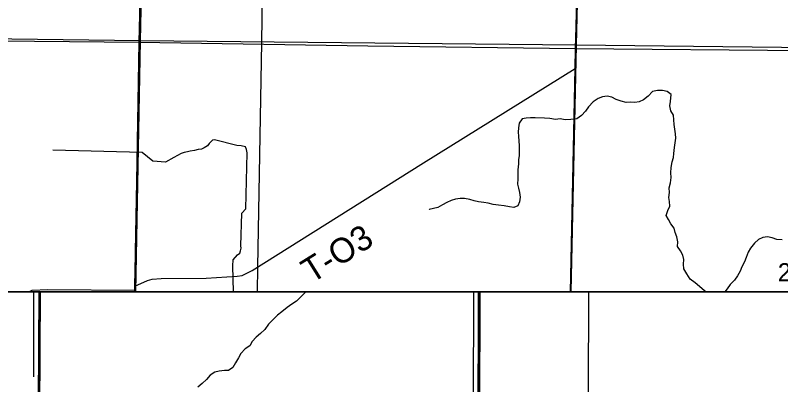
# Model space of a CAD drawing. Extents: x -6.2 to 37.4, y 0.2 to 22.2.
# Drawn here: x 5.676 to 6.554, y 17.601 to 18.025 of the extents above; entities that cross this region are included whole.
import ezdxf

# ---------------------------------------------------------------- set-up
doc = ezdxf.new("R2010")
doc.units = 0
for name, color, linetype in [('GM_X_County_Road', 7, 'Continuous'), ('GM_X_Minor_River', 7, 'Continuous'), ('GM_X_Rail_Line', 7, 'Continuous'), ('GM_X_Section', 7, 'Continuous'), ('GM_X_Section_Text', 7, 'Continuous'), ('GM_X_State_Route', 7, 'Continuous'), ('GM_X_Township_Road', 7, 'Continuous'), ('GM_X_Township_Road_Text', 7, 'Continuous'), ('GM_X_US_Shield', 7, 'Continuous'), ('SH_Border', 7, 'Continuous'), ('SH_Cut_Line', 7, 'Continuous')]:
    doc.layers.add(name, color=color, linetype=linetype)

msp = doc.modelspace()

# ---------------------------------------------------------------- linework, layer by layer
at = {"layer": 'GM_X_County_Road'}
msp.add_lwpolyline([(5.44297, 17.99748), (5.45798, 17.99734), (5.81851, 17.99391), (6.08058, 17.98981), (6.31898, 17.9868), (6.58277, 17.9842), (6.78688, 17.98297), (6.82357, 17.99459)], dxfattribs=at)
at = {"layer": 'GM_X_Minor_River'}
for p, q in [((5.69738, 17.70742), (5.69714, 17.61009)), ((6.20166, 17.70742), (6.20111, 17.43298))]:
    msp.add_line(p, q, dxfattribs=at)
for points in [[(6.46898, 17.70742), (6.46647, 17.70917), (6.45605, 17.71773), (6.45047, 17.7222), (6.44662, 17.72816), (6.44314, 17.73392), (6.44268, 17.73924), (6.44298, 17.74454), (6.44177, 17.74969), (6.43903, 17.75449), (6.43591, 17.75948), (6.43602, 17.76479), (6.43501, 17.7705), (6.43322, 17.77566), (6.432, 17.78043), (6.42794, 17.78544), (6.42539, 17.79043), (6.42284, 17.79522), (6.42485, 17.80068), (6.42704, 17.80595), (6.42677, 17.81107), (6.42592, 17.81583), (6.42661, 17.82132), (6.42634, 17.82683), (6.4276, 17.83268), (6.42867, 17.83854), (6.42822, 17.84405), (6.42835, 17.85031), (6.4298, 17.85654), (6.43104, 17.86145), (6.43171, 17.86637), (6.43242, 17.87318), (6.43291, 17.87829), (6.43397, 17.88377), (6.43351, 17.88891), (6.43267, 17.89423), (6.43202, 17.89937), (6.43157, 17.90488), (6.43112, 17.9102), (6.428, 17.91519), (6.42698, 17.92072), (6.42785, 17.92582), (6.42858, 17.93377), (6.42373, 17.93728), (6.41846, 17.93853), (6.41278, 17.93845), (6.40708, 17.93724), (6.40204, 17.93184), (6.39685, 17.92777), (6.39169, 17.9256), (6.38694, 17.92474), (6.38184, 17.92504), (6.37691, 17.92475), (6.37126, 17.9262), (6.36525, 17.92821), (6.36039, 17.93097), (6.35511, 17.93202), (6.3496, 17.93118), (6.34483, 17.92938), (6.33907, 17.92532), (6.33384, 17.91974), (6.33033, 17.91469), (6.32568, 17.90966), (6.32031, 17.90597), (6.31329, 17.90516), (6.30703, 17.90472), (6.30138, 17.90597), (6.29569, 17.90533), (6.28947, 17.9064), (6.28342, 17.90671), (6.27263, 17.90693), (6.26715, 17.90723), (6.26241, 17.90675), (6.25766, 17.90609), (6.25415, 17.90085), (6.25328, 17.89555), (6.25318, 17.89081), (6.25327, 17.88607), (6.25371, 17.88018), (6.25437, 17.87523), (6.25407, 17.86993), (6.25413, 17.86405), (6.25346, 17.85894), (6.25355, 17.85419), (6.25284, 17.84757), (6.25255, 17.84264), (6.25263, 17.83733), (6.25231, 17.83107), (6.25335, 17.82631), (6.25476, 17.82135), (6.25522, 17.81622), (6.25473, 17.81092), (6.25273, 17.80603), (6.24796, 17.80423), (6.24306, 17.80508), (6.23703, 17.80634), (6.23061, 17.80704), (6.22419, 17.80755), (6.21854, 17.80918), (6.21364, 17.81004)], [(5.92677, 17.70742), (5.92595, 17.73727), (5.9261, 17.74429), (5.93113, 17.74987), (5.93402, 17.75209), (5.93464, 17.75455), (5.93527, 17.75776), (5.93513, 17.76023), (5.9363, 17.79795), (5.94075, 17.80261), (5.94229, 17.86707), (5.94142, 17.8707), (5.94035, 17.87375), (5.93526, 17.87499), (5.93054, 17.87528), (5.90494, 17.88205), (5.90266, 17.88153), (5.89879, 17.87781), (5.89684, 17.875), (5.89301, 17.87262), (5.88976, 17.87135), (5.88596, 17.87067), (5.88197, 17.8698), (5.87703, 17.86876), (5.8738, 17.86826), (5.87, 17.86739), (5.86676, 17.86631), (5.85814, 17.86155), (5.84857, 17.85624), (5.83402, 17.85729), (5.82192, 17.86721), (5.71959, 17.87022)], [(6.21364, 17.81004), (6.20741, 17.81092), (6.20251, 17.81197), (6.19743, 17.8134), (6.19159, 17.81446), (6.18648, 17.81456), (6.18136, 17.81391), (6.17622, 17.81249), (6.17124, 17.80994), (6.16626, 17.80719), (6.16109, 17.80426), (6.15577, 17.80323), (6.15082, 17.80181), (6.15121, 17.80237)], [(6.55569, 17.76714), (6.54964, 17.76745), (6.54438, 17.76964), (6.5391, 17.7705), (6.53379, 17.76985), (6.52882, 17.76749), (6.524, 17.76322), (6.51953, 17.75781), (6.51678, 17.75293), (6.51458, 17.74709), (6.51258, 17.74182), (6.50962, 17.73638), (6.50781, 17.7313), (6.50449, 17.72605), (6.50097, 17.721), (6.49614, 17.71597), (6.49282, 17.71111), (6.49021, 17.70742)], [(6.00944, 17.70742), (6.00912, 17.70723), (6.00383, 17.70169), (5.99876, 17.6969), (5.99353, 17.69326), (5.98811, 17.68943), (5.98209, 17.68468), (5.97723, 17.68083), (5.97254, 17.67604), (5.96687, 17.67032), (5.96252, 17.66438), (5.95744, 17.65959)], [(5.95744, 17.65959), (5.95258, 17.65556), (5.94808, 17.65076), (5.94546, 17.64571), (5.94005, 17.64226), (5.93495, 17.63672), (5.93234, 17.63186), (5.92894, 17.62608), (5.92575, 17.62086), (5.9209, 17.61721), (5.91616, 17.61716), (5.91027, 17.61676), (5.90531, 17.61558), (5.89989, 17.61194), (5.89576, 17.60694), (5.89069, 17.60253), (5.88583, 17.59831)]]:
    msp.add_lwpolyline(points, dxfattribs=at)
at = {"layer": 'GM_X_Rail_Line'}
for points in [[(5.95421, 17.70742), (5.95464, 17.73589), (5.95897, 17.99343), (5.96235, 18.24518), (5.97247, 18.73855), (5.97681, 19.01971), (5.98659, 19.63824), (5.98805, 19.72376), (5.99343, 19.98571), (6.00043, 20.49066), (6.01007, 20.99513), (6.012, 21.10742)], [(5.20332, 18.78785), (5.18706, 18.77926), (5.14655, 18.76074), (5.10723, 18.74484), (5.08086, 18.73488), (5.08086, 17.70742), (6.81845, 17.70742)], [(6.31856, 15.3389), (6.32321, 16.06776), (6.32739, 16.56932), (6.32971, 16.59442), (6.3325, 16.61347), (6.33861, 16.64043), (6.36296, 16.73186), (6.36763, 16.74863), (6.37346, 16.77072), (6.37609, 16.79136), (6.37782, 16.81051), (6.3756, 16.83566), (6.37132, 16.85572), (6.36631, 16.872), (6.35505, 16.90208), (6.33963, 16.94196), (6.33622, 16.95652), (6.33343, 16.97605), (6.33111, 16.99836), (6.32971, 17.02811), (6.33343, 17.47435), (6.33417, 17.70742)]]:
    msp.add_lwpolyline(points, dxfattribs=at)
msp.add_lwpolyline([(7.2147, 17.70742), (5.08086, 17.70742), (5.08086, 17.58453), (5.20184, 17.58249), (5.70294, 17.57023), (6.20697, 17.56634), (6.71201, 17.56218), (7.21485, 17.56218)], close=True, dxfattribs=at)
at = {"layer": 'GM_X_Section'}
for points in [[(5.32975, 18.50593), (5.83036, 18.49858), (5.81937, 17.99536), (5.31894, 18.00175)], [(5.83036, 18.49858), (6.33154, 18.49141), (6.31963, 17.9903), (5.81937, 17.99536)], [(6.33154, 18.49141), (6.83443, 18.48586), (6.82474, 17.99671), (6.82431, 17.98462), (6.31963, 17.9903)]]:
    msp.add_lwpolyline(points, close=True, dxfattribs=at)
at = {"layer": 'GM_X_State_Route'}
for p, q in [((5.81354, 17.71419), (5.8142, 17.75045)), ((5.81345, 17.70963), (5.81354, 17.71419)), ((5.81341, 17.70742), (5.81345, 17.70963)), ((6.2074, 17.67063), (6.20751, 17.70742)), ((6.20709, 17.56607), (6.2074, 17.67063))]:
    msp.add_line(p, q, dxfattribs=at)
msp.add_lwpolyline([(5.8142, 17.75045), (5.81426, 17.75352), (5.81573, 17.83399), (5.81851, 17.99391), (5.82356, 18.19747), (5.82441, 18.24572), (5.83009, 18.56933), (5.83681, 18.72749)], dxfattribs=at)
at = {"layer": 'GM_X_Township_Road'}
for p, q in [((5.81345, 17.70963), (5.81354, 17.71419)), ((5.70306, 17.56995), (5.70374, 17.70742))]:
    msp.add_line(p, q, dxfattribs=at)
for points in [[(6.31307, 17.70742), (6.31848, 17.96364), (6.31898, 17.9868), (6.3195, 18.01166), (6.32489, 18.23861), (6.33938, 18.70845)], [(5.81354, 17.71419), (5.82784, 17.72063), (5.83335, 17.72208), (5.84379, 17.7227), (5.89535, 17.72314), (5.93063, 17.7257), (5.93652, 17.72638), (5.94797, 17.73193), (6.14431, 17.85532), (6.31848, 17.96364)], [(5.69153, 17.70742), (5.69177, 17.70767), (5.69577, 17.70932), (5.71379, 17.71021), (5.81345, 17.70963)]]:
    msp.add_lwpolyline(points, dxfattribs=at)
at = {"layer": 'GM_X_US_Shield'}
for points in [[(5.31339, 17.70742), (5.81405, 17.70742), (5.81937, 17.99536), (5.31894, 18.00175)], [(5.81405, 17.70742), (6.31355, 17.70742), (6.31963, 17.9903), (5.81937, 17.99536)], [(6.31355, 17.70742), (6.81927, 17.70742), (6.82431, 17.98462), (6.31963, 17.9903)], [(5.70485, 17.70742), (5.20292, 17.70742), (5.20265, 17.58289), (5.20682, 17.58263), (5.70428, 17.571)], [(6.20899, 17.70742), (5.70485, 17.70742), (5.70428, 17.571), (5.7075, 17.57094), (6.20873, 17.56928)], [(6.71326, 17.70742), (6.20899, 17.70742), (6.20873, 17.56928), (6.71428, 17.56583)]]:
    msp.add_lwpolyline(points, close=True, dxfattribs=at)
at = {"layer": 'SH_Border'}
msp.add_line((5.08086, 17.70742), (8.48086, 17.70742), dxfattribs=at)
at = {"layer": 'SH_Cut_Line'}
msp.add_lwpolyline([(8.48086, 14.54119), (8.48086, 17.70742), (5.08086, 17.70742), (5.08086, 14.57317)], dxfattribs=at)

# ---------------------------------------------------------------- texts
at = {"layer": 'GM_X_Section_Text'}
msp.add_text('24', height=0.020928, rotation=0.00001, dxfattribs=at).set_placement((6.55073, 17.7195))
at = {"layer": 'GM_X_Township_Road_Text'}
msp.add_text('T-O3', height=0.028409, rotation=31.9381, dxfattribs=at).set_placement((6.01601, 17.71659))

doc.saveas('drawing.dxf')
